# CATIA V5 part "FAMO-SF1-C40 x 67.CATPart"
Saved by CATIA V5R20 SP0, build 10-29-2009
Part number: FAMO-SF1-C40 x 67
Definition: NONE
Nomenclature: FAMO-SF1-C40 x 67
Source: Unknown
Description: FAMO-SF1-C40 x 67
Bounding box of the stored display mesh (mm): x -37 to 30, y -31.5 to 31.5, z -31.5 to 31.5
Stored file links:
  C:\Users\Utente\Desktop\IO LAVORO\3D X SITO CF\X SITO\FAMO\FAMO-SF1-C40 x 67.CATPart

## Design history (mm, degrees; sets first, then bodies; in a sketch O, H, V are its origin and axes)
Body1 "FAMO-SF1-C40 x 67" (main body)
  Solid1: solid without history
